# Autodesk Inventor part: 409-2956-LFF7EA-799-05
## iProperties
Created: 2010-11
Part Number: 409-2956-LFF7EA-799-05
Material: 3/4" OD TUBE - SS
Document SubType Name: Modeling
Designer: S. Boerckel
Engineer: Steve Boerckel
Mass: 727.021 g
Surface Area: 1091.79 cm^2
Volume: 89.9779 cm^3
Density: 8.08 g/cm^3
Description: DRAIN TUBING
LGTH: 39.254 in
Author: S. Boerckel
Revision Number: 0
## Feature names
1. TaggingFeature1
